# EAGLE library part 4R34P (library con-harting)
CONNECTOR
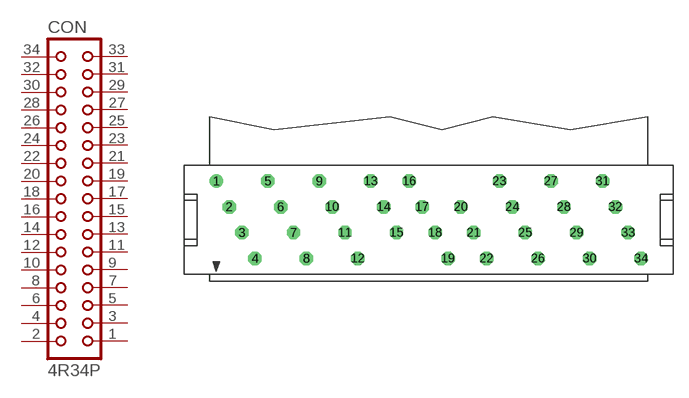
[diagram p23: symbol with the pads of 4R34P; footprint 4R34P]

Designator prefix CON

## 4R34P (OC_FARNELL: unknown; OC_NEWARK: unknown)  [4R34P]
1  1  pas
2  2  pas
3  3  pas
4  4  pas
5  5  pas
6  6  pas
7  7  pas
8  8  pas
9  9  pas
10  10  pas
11  11  pas
12  12  pas
13  13  pas
14  14  pas
15  15  pas
16  16  pas
17  17  pas
18  18  pas
19  19  pas
20  20  pas
21  21  pas
22  22  pas
23  23  pas
24  24  pas
25  25  pas
26  26  pas
27  27  pas
28  28  pas
29  29  pas
30  30  pas
31  31  pas
32  32  pas
33  33  pas
34  34  pas

## Footprint 4R34P (pad centres in mm)
CONNECTOR
drill 0.813 round: 1 -20.955,3.81
drill 0.813 octagon: 2 -19.685,1.27; 3 -18.415,-1.27; 4 -17.145,-3.81; 5 -15.875,3.81; 6 -14.605,1.27; 7 -13.335,-1.27; 8 -12.065,-3.81; 9 -10.795,3.81; 10 -9.525,1.27; 11 -8.255,-1.27; 12 -6.985,-3.81; 13 -5.715,3.81; 14 -4.445,1.27; 15 -3.175,-1.27; 16 -1.905,3.81; 17 -0.635,1.27; 18 0.635,-1.27; 19 1.905,-3.81; 20 3.175,1.27; 21 4.445,-1.27; 22 5.715,-3.81; 23 6.985,3.81; 24 8.255,1.27; 25 9.525,-1.27; 26 10.795,-3.81; 27 12.065,3.81; 28 13.335,1.27; 29 14.605,-1.27; 30 15.875,-3.81; 31 17.145,3.81; 32 18.415,1.27; 33 19.685,-1.27; 34 20.955,-3.81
